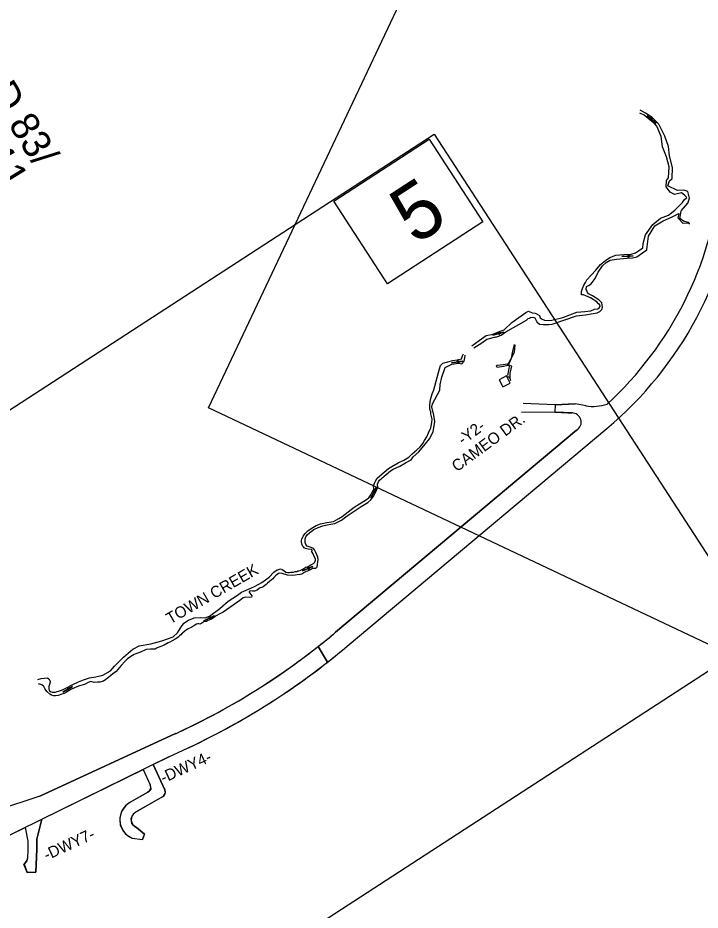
# Model space of a CAD drawing. Extents: x 555292 to 2368606, y 503623 to 1171444.
# Drawn here: x 2359845 to 2361046, y 1163245 to 1164815 of the extents above; entities that cross this region are included whole.
import ezdxf

# ---------------------------------------------------------------- set-up
doc = ezdxf.new("R2010")
doc.units = 0
for name, color, linetype in [('Default', 7, 'Continuous'), ('Exist Hydro Stream or Body of Water', 7, 'Continuous'), ('Exist Roads EOT', 7, 'Continuous'), ('Prop DSN Text', 7, 'Continuous'), ('Prop EOT', 7, 'Continuous'), ('Prop Shade Light', 7, 'Continuous'), ('Sheet North Arrow CELL', 7, 'Continuous'), ('Sheet Title CELL', 7, 'Continuous')]:
    doc.layers.add(name, color=color, linetype=linetype)

msp = doc.modelspace()

# ---------------------------------------------------------------- linework, layer by layer
at = {"layer": 'Default'}
for p, q in [((2360960.4, 1164635.9), (2360960.4, 1164635.9)), ((2360917.7, 1164395.2), (2360917.7, 1164395.2)), ((2360690.4, 1164259.1), (2360690.4, 1164259.1)), ((2360617.9, 1164209.3), (2360617.9, 1164209.3)), ((2360470.8, 1163979.1), (2360470.8, 1163979.1)), ((2360354.8, 1163845.5), (2360354.8, 1163845.5)), ((2360181.3, 1163758.1), (2360181.3, 1163758.1)), ((2359932.6, 1163633.2), (2359932.6, 1163633.2))]:
    msp.add_line(p, q, dxfattribs=at)
for points in [[(2360958.9, 1164634.1), (2360958, 1164635.9), (2360956.9, 1164637.6), (2360955.6, 1164639.3), (2360954.2, 1164640.8), (2360952.6, 1164642.2), (2360968.1, 1164629.5), (2360952.6, 1164642.2), (2360954.3, 1164640.9), (2360956.1, 1164639.9), (2360957.9, 1164639), (2360959.9, 1164638.2), (2360961.8, 1164637.6)], [(2360917.5, 1164397.5), (2360919.5, 1164396.9), (2360921.5, 1164396.4), (2360923.6, 1164396), (2360925.6, 1164395.8), (2360927.7, 1164395.9), (2360907.7, 1164394.6), (2360927.7, 1164395.9), (2360925.6, 1164395.7), (2360923.6, 1164395.2), (2360921.6, 1164394.6), (2360919.7, 1164393.9), (2360917.8, 1164393)], [(2360689.7, 1164261.3), (2360691.7, 1164261), (2360693.8, 1164261), (2360695.9, 1164261.1), (2360698, 1164261.4), (2360699.9, 1164261.9), (2360680.8, 1164256.2), (2360699.9, 1164261.9), (2360698, 1164261.3), (2360696.1, 1164260.4), (2360694.3, 1164259.3), (2360692.6, 1164258.2), (2360691, 1164256.9)], [(2360617.6, 1164211.5), (2360619.6, 1164211), (2360621.6, 1164210.7), (2360623.7, 1164210.5), (2360625.8, 1164210.5), (2360627.8, 1164210.7), (2360608.1, 1164207.8), (2360627.8, 1164210.7), (2360625.8, 1164210.3), (2360623.8, 1164209.7), (2360621.9, 1164209), (2360620, 1164208), (2360618.3, 1164207)], [(2360468.7, 1163980.1), (2360470.3, 1163981.5), (2360471.8, 1163982.9), (2360473.1, 1163984.5), (2360474.3, 1163986.2), (2360475.3, 1163988), (2360466.3, 1163970.2), (2360475.3, 1163988), (2360474.5, 1163986.2), (2360473.8, 1163984.2), (2360473.3, 1163982.1), (2360473, 1163980.1), (2360472.8, 1163978.1)], [(2360353.9, 1163847.6), (2360355.9, 1163847.6), (2360358, 1163847.8), (2360360.1, 1163848.2), (2360362.1, 1163848.7), (2360364, 1163849.5), (2360345.6, 1163841.5), (2360364, 1163849.5), (2360362.1, 1163848.6), (2360360.4, 1163847.5), (2360358.7, 1163846.2), (2360357.1, 1163844.8), (2360355.7, 1163843.4)], [(2360180.3, 1163760.2), (2360182.3, 1163760.3), (2360184.4, 1163760.6), (2360186.4, 1163761.1), (2360188.4, 1163761.7), (2360190.3, 1163762.6), (2360172.4, 1163753.7), (2360190.3, 1163762.6), (2360188.5, 1163761.6), (2360186.8, 1163760.4), (2360185.2, 1163759.1), (2360183.7, 1163757.6), (2360182.3, 1163756.1)], [(2359931.5, 1163635.2), (2359933.5, 1163635.5), (2359935.5, 1163636), (2359937.5, 1163636.6), (2359939.4, 1163637.4), (2359941.2, 1163638.4), (2359924.1, 1163628.1), (2359941.2, 1163638.4), (2359939.5, 1163637.3), (2359937.9, 1163635.9), (2359936.4, 1163634.5), (2359935, 1163632.9), (2359933.8, 1163631.3)]]:
    msp.add_lwpolyline(points, dxfattribs=at)
at = {"layer": 'Exist Hydro Stream or Body of Water'}
msp.add_line((2360706.9, 1164185.3), (2360710.5, 1164204.2), dxfattribs=at)
for points in [[(2360969.1, 1164624), (2360965.8, 1164628.3), (2360957.7, 1164634.6), (2360946.9, 1164643.4), (2360939.2, 1164646.9)], [(2360973, 1164627.5), (2360969, 1164632), (2360961.4, 1164639.4), (2360949.6, 1164647.1), (2360940, 1164652.2)], [(2360937.2, 1164404.8), (2360944.9, 1164410), (2360945, 1164417.6), (2360949.6, 1164432.9), (2360962.4, 1164451.2), (2360975.8, 1164462.4), (2360989.6, 1164467.7), (2361001.1, 1164476.1), (2361014.7, 1164489.6), (2361017.7, 1164494.8), (2361022.4, 1164498.9), (2361017.8, 1164502.8), (2361012.6, 1164507), (2361000.3, 1164504.1), (2360992.7, 1164508.2), (2360985.8, 1164517.6), (2360986.3, 1164528.3), (2360989.9, 1164533.5), (2360991, 1164552.5), (2360986.5, 1164570.3), (2360979.3, 1164587.7), (2360977, 1164605.8), (2360969.1, 1164624)], [(2361011.9, 1164475), (2361023.7, 1164488.8), (2361026.9, 1164497.4), (2361023.6, 1164509.2), (2361016.6, 1164511.7), (2361005.5, 1164510.9), (2360988.8, 1164519.2), (2360991.5, 1164528), (2360996.3, 1164532.1), (2360997.1, 1164551.2), (2360991.4, 1164572.2), (2360989.7, 1164588.6), (2360983.6, 1164606.4), (2360973, 1164627.5)], [(2360944.4, 1164401.3), (2360951.6, 1164406.4), (2360952.6, 1164411.7), (2360954.4, 1164430.6), (2360966, 1164448.7), (2360980.5, 1164457.6), (2360995.1, 1164464.1), (2361008.3, 1164470.6)], [(2361026.8, 1164451.8), (2361026.1, 1164452.1), (2361024.6, 1164453.5), (2361015.4, 1164453), (2361006.9, 1164462.2), (2361008.5, 1164470.3)], [(2361027.1, 1164452.4), (2361027.1, 1164452.8), (2361025.1, 1164454.9), (2361016, 1164457.1), (2361009.7, 1164461.8), (2361011.9, 1164474.6)], [(2360784.5, 1164282.6), (2360803.9, 1164287.7), (2360828.8, 1164297.1), (2360842.4, 1164298), (2360852.9, 1164299.1), (2360859.9, 1164302.3), (2360865.6, 1164302.6), (2360867.7, 1164304.7), (2360869.8, 1164306.9), (2360868.9, 1164309.7), (2360866.7, 1164311.6), (2360863.8, 1164315), (2360852.6, 1164322.1), (2360840.4, 1164327.2), (2360836.9, 1164327.5), (2360836.8, 1164333.2), (2360838.7, 1164338.5), (2360841, 1164344.2), (2360843.9, 1164349), (2360845.9, 1164354), (2360853.6, 1164361.9), (2360861.8, 1164370.8), (2360870.4, 1164380.6), (2360878.8, 1164387.9), (2360886.4, 1164392.9), (2360897.4, 1164397), (2360911.3, 1164398.3), (2360924.2, 1164399), (2360931.9, 1164401.2), (2360937.2, 1164404.8)], [(2360785.3, 1164276), (2360805.6, 1164282.6), (2360828.2, 1164290.5), (2360843.9, 1164292), (2360853.9, 1164293.8), (2360864.1, 1164295.9), (2360868.8, 1164298.2), (2360872.3, 1164301.7), (2360873.9, 1164305.8), (2360873.4, 1164309.7), (2360872.3, 1164313.4), (2360867.4, 1164318.5), (2360856.3, 1164325.6), (2360849.3, 1164329.3), (2360847.1, 1164331.6), (2360846.6, 1164334.1), (2360844.7, 1164336.5), (2360845.8, 1164341.8), (2360848.9, 1164344.1), (2360853.9, 1164346.7), (2360861.1, 1164356.2), (2360866, 1164367.4), (2360873.7, 1164378.2), (2360880.1, 1164384.5), (2360887.4, 1164388.6), (2360898.6, 1164390.4), (2360916.5, 1164391.7), (2360926.8, 1164392.4), (2360934.3, 1164394.2), (2360944.4, 1164401.3)], [(2360714.1, 1164279), (2360738.9, 1164296.4), (2360743.4, 1164298.9), (2360749.7, 1164295.5), (2360755.2, 1164294.9), (2360758.9, 1164293.3), (2360762.6, 1164291), (2360764, 1164287.2), (2360767.5, 1164284.5), (2360771.7, 1164283.1), (2360778.7, 1164282), (2360784.5, 1164282.6)], [(2360643.9, 1164237.7), (2360656.8, 1164247.2), (2360668.9, 1164256.1), (2360681.1, 1164257.9), (2360693.9, 1164263.3), (2360700.4, 1164266), (2360714.1, 1164279)], [(2360703.6, 1164262.5), (2360739.8, 1164282.9), (2360742.9, 1164285.7), (2360745, 1164286.5), (2360747.2, 1164287.3), (2360749.9, 1164288.1), (2360752.6, 1164287.5), (2360754.5, 1164286.8), (2360755.9, 1164284.8), (2360757.9, 1164279.7), (2360762.7, 1164275.6), (2360770, 1164275.4), (2360779, 1164275.3), (2360785.3, 1164276)], [(2360686.3, 1164253.1), (2360695.5, 1164256.3), (2360703.6, 1164262.5)], [(2360647.3, 1164234.3), (2360661.1, 1164242.7), (2360670.3, 1164249.2), (2360686, 1164253.2)], [(2360706.8, 1164184.5), (2360707.4, 1164183.4), (2360708.6, 1164183.4), (2360710.5, 1164180.7), (2360712.1, 1164176.4), (2360711.5, 1164182.8), (2360711.2, 1164189.3), (2360714, 1164201.6), (2360706.3, 1164202.8), (2360719.1, 1164226.4), (2360720.2, 1164239.4)], [(2360709.5, 1164206.6), (2360713.7, 1164215.7), (2360715.3, 1164225.4), (2360718.8, 1164240.1)], [(2360581.1, 1164175.5), (2360586.8, 1164197.3), (2360588.6, 1164203.2), (2360593, 1164207.2), (2360610.1, 1164211.9), (2360618.1, 1164213.1), (2360625.7, 1164214.7), (2360627.5, 1164220), (2360629.1, 1164223.8)], [(2360587.6, 1164159.9), (2360588, 1164169.8), (2360590.7, 1164182.5), (2360596.9, 1164199.8), (2360608.8, 1164205.2), (2360620.4, 1164207), (2360626, 1164206.1), (2360630.3, 1164210.7), (2360631.5, 1164216.8), (2360632, 1164221.1)], [(2360686.7, 1164202.3), (2360688.6, 1164203.9), (2360699, 1164204.7), (2360709.3, 1164206.4)], [(2360686.7, 1164202), (2360688.4, 1164200.4), (2360699.4, 1164202.1), (2360710.1, 1164204.1)], [(2360711, 1164171.9), (2360704.7, 1164184.6), (2360691.7, 1164177.8), (2360698.6, 1164165.7), (2360711, 1164171.9)], [(2360539, 1164047.7), (2360546.7, 1164054.6), (2360553, 1164059.8), (2360557.5, 1164066), (2360560.6, 1164071), (2360564.6, 1164077.8), (2360567.8, 1164084.8), (2360571.4, 1164093.5), (2360573.3, 1164102.7), (2360573.8, 1164108.8), (2360571.8, 1164118.1), (2360571.5, 1164121.6), (2360569.8, 1164126.5), (2360569.7, 1164131.9), (2360570.3, 1164140), (2360571.7, 1164145.1), (2360574.2, 1164153), (2360576.8, 1164160.1), (2360581.1, 1164175.5)], [(2360540.7, 1164042.2), (2360550.3, 1164051.2), (2360561.7, 1164064.8), (2360569.4, 1164073.9), (2360575.5, 1164086.3), (2360578.8, 1164104.4), (2360577.1, 1164115.5), (2360573.2, 1164130.3), (2360574.4, 1164135.5), (2360587.6, 1164159.9)], [(2360436.5, 1163953.6), (2360446.1, 1163959.8), (2360456.6, 1163966.4), (2360462.3, 1163970.2), (2360466.1, 1163975.7), (2360471.2, 1163985.8), (2360470.6, 1163990.5), (2360472.7, 1163995.8), (2360474.7, 1164000.7), (2360477.4, 1164004.6), (2360481.8, 1164009), (2360497.3, 1164022), (2360503, 1164025.5), (2360514.1, 1164031.6), (2360524.3, 1164036.3), (2360532.7, 1164041.6), (2360539, 1164047.7)], [(2360438.4, 1163948), (2360449.3, 1163954.9), (2360460.5, 1163961.9), (2360466.2, 1163966.6), (2360470.6, 1163973), (2360475.2, 1163982), (2360478.2, 1163988.8), (2360477.7, 1163994.2), (2360479.3, 1163998.2), (2360481.4, 1164001.2), (2360485.4, 1164005.1), (2360500.4, 1164017.8), (2360505.5, 1164020.9), (2360517.2, 1164026), (2360526.8, 1164031.8), (2360537, 1164036.9), (2360540.7, 1164042.2)], [(2360344.8, 1163897.3), (2360347, 1163902.7), (2360350.6, 1163907.7), (2360355.3, 1163912), (2360360.9, 1163916.2), (2360369.8, 1163921.6), (2360377.2, 1163924.2), (2360388.7, 1163926.7), (2360400.2, 1163928.4), (2360410, 1163934.1), (2360415.5, 1163937.6), (2360436.5, 1163953.6)], [(2360350.5, 1163898.3), (2360351.4, 1163901.7), (2360354.1, 1163905.2), (2360358.9, 1163909.4), (2360365.6, 1163914.3), (2360373.6, 1163917.9), (2360381.4, 1163920.8), (2360389, 1163922.8), (2360395.4, 1163923.8), (2360402.8, 1163925.2), (2360414.5, 1163931.2), (2360424.1, 1163938.5), (2360438.2, 1163947.9)], [(2360340.6, 1163835.5), (2360344.6, 1163836.5), (2360348.3, 1163838.9), (2360352.6, 1163841.3), (2360355.4, 1163842), (2360357.6, 1163842.8), (2360359.8, 1163843.9), (2360363.6, 1163846.3), (2360365.6, 1163846.6), (2360367.7, 1163846.5), (2360369, 1163846.5), (2360370.1, 1163846.8), (2360370.9, 1163847.4), (2360371.4, 1163848.6), (2360372, 1163852.9), (2360372.7, 1163857.6), (2360373.2, 1163861.9), (2360372.6, 1163865.9), (2360371.2, 1163869.7), (2360369.4, 1163873.9), (2360367.1, 1163878.5), (2360364.9, 1163880.9), (2360363.7, 1163881.9), (2360359, 1163883.2), (2360353.9, 1163884.9), (2360351.6, 1163888), (2360350.5, 1163891.4), (2360350.5, 1163898.3)], [(2360341.9, 1163842.4), (2360346.2, 1163844.7), (2360351.9, 1163848), (2360355.9, 1163849.3), (2360360.6, 1163852.1), (2360362.8, 1163853.8), (2360365.4, 1163854.9), (2360367.7, 1163857.1), (2360368.4, 1163860.6), (2360368.4, 1163862.8), (2360366.6, 1163867.1), (2360364.8, 1163871.5), (2360362.9, 1163874.6), (2360361.7, 1163876.2), (2360362.7, 1163877.1), (2360362.6, 1163878.2), (2360361.9, 1163879.3), (2360361.3, 1163879.5), (2360356, 1163880), (2360353.3, 1163880.4), (2360351, 1163881.3), (2360349, 1163882.5), (2360347.4, 1163883.8), (2360345.9, 1163885.5), (2360345, 1163887.8), (2360344.3, 1163891.4), (2360344, 1163895.3), (2360344.8, 1163897.3)], [(2359880.3, 1163650.6), (2359885.9, 1163652.5), (2359891.1, 1163653.2), (2359897, 1163653.7), (2359899.2, 1163651.8), (2359901.5, 1163647.4), (2359901.2, 1163643.3), (2359899.4, 1163638), (2359899.2, 1163634.4), (2359900, 1163631), (2359902.2, 1163629.4), (2359905.5, 1163628.3), (2359911.2, 1163628.1), (2359914.3, 1163629.3), (2359920.3, 1163631.4), (2359924.8, 1163633.2), (2359930.5, 1163636), (2359940.4, 1163641.5), (2359951.5, 1163646.2), (2359960.3, 1163650), (2359971, 1163653.8), (2359982.2, 1163655.3), (2359994.2, 1163658.4), (2360008.1, 1163666.1), (2360014.7, 1163674.3), (2360030.5, 1163689.6), (2360047.2, 1163703.9), (2360058.6, 1163709.6), (2360079.1, 1163713.3), (2360098.4, 1163718.7), (2360118.4, 1163725.7), (2360125.8, 1163732.7), (2360131.7, 1163742.1), (2360137, 1163749.8), (2360145.3, 1163754.9), (2360155.1, 1163759.1), (2360165.5, 1163759.9), (2360174.6, 1163759.2), (2360182.3, 1163762.2), (2360200.2, 1163775.5), (2360215.2, 1163788.6), (2360231.5, 1163799), (2360238.7, 1163804.5), (2360250.8, 1163809.8), (2360261.5, 1163814.3), (2360274.5, 1163821.4), (2360287, 1163830.7), (2360295.2, 1163839.3), (2360301.1, 1163843.7), (2360303.4, 1163844)], [(2360303.4, 1163844), (2360307.1, 1163845.2), (2360310, 1163844.3), (2360312.7, 1163842.1), (2360316.7, 1163839.7), (2360320.1, 1163838.8), (2360322.7, 1163839), (2360325, 1163839.5), (2360327.5, 1163839.7), (2360330.1, 1163839.7), (2360332.8, 1163840.6), (2360334.3, 1163840.4), (2360336, 1163840.7), (2360337.7, 1163841.9), (2360339.3, 1163841.9), (2360341.9, 1163842.4)], [(2360305.3, 1163837.8), (2360303.3, 1163836.9), (2360301.4, 1163835.5), (2360298.3, 1163832.8), (2360295.4, 1163830.2), (2360293.3, 1163828), (2360290.8, 1163825.2), (2360288, 1163823.1), (2360284.1, 1163819.8), (2360281.8, 1163818), (2360276.8, 1163813.9), (2360274.5, 1163812.6), (2360271.3, 1163811.7), (2360269.4, 1163810.5), (2360265.8, 1163807.6), (2360261.4, 1163805.9), (2360257.7, 1163806.2), (2360254.8, 1163806.4), (2360253, 1163806), (2360252.2, 1163805.4), (2360252.1, 1163804.3), (2360253.1, 1163802.5), (2360256.5, 1163797.7), (2360256.2, 1163795.6), (2360252.6, 1163794.6), (2360246.2, 1163795.2), (2360241.5, 1163794.1), (2360235.5, 1163789.8), (2360229.4, 1163785.2), (2360223.9, 1163781.3), (2360206.1, 1163769), (2360200.1, 1163766), (2360193.7, 1163762.5), (2360192, 1163761.3), (2360190.8, 1163760.1), (2360188.2, 1163758.3), (2360185.8, 1163756.6), (2360183, 1163755.5), (2360179.3, 1163754.4), (2360176.6, 1163752.8), (2360175.5, 1163752.4), (2360171.8, 1163751.9), (2360170.1, 1163751), (2360168.6, 1163750), (2360165.3, 1163748.2), (2360163.2, 1163748.5), (2360161.6, 1163748.4), (2360159.4, 1163747.8), (2360156.3, 1163745.9), (2360150.9, 1163742.8), (2360143.5, 1163739), (2360138.8, 1163735.7), (2360135.1, 1163732.9), (2360134, 1163732.1), (2360131.5, 1163729.3), (2360129.1, 1163727.4), (2360127.2, 1163725.2), (2360124.8, 1163723.5), (2360121.5, 1163721.4), (2360116.5, 1163718.5), (2360112.5, 1163716.2), (2360109.3, 1163714.9), (2360102.3, 1163711), (2360090.3, 1163706.3), (2360086.4, 1163704.2), (2360078.5, 1163703.8), (2360070.7, 1163703.2), (2360060.5, 1163698.9), (2360052.6, 1163695.9), (2360049.3, 1163694.4), (2360043.4, 1163690.8), (2360037.6, 1163686.8), (2360033.2, 1163682.3), (2360026.7, 1163675.2), (2360018.1, 1163664.6), (2360011.9, 1163660.4), (2360008.5, 1163657.8), (2360004.1, 1163654.4), (2359999.4, 1163650.5), (2359995.4, 1163647.8), (2359989, 1163646.1), (2359984.8, 1163645.7), (2359979.2, 1163645.6), (2359973.2, 1163646.8), (2359968.8, 1163645.3), (2359961.9, 1163642), (2359953.4, 1163639.5), (2359948.4, 1163637.8), (2359943.1, 1163635.4), (2359939, 1163633.4), (2359930.3, 1163628.2), (2359926.4, 1163625.9), (2359922.4, 1163624.5), (2359915.6, 1163622.4), (2359911.4, 1163621.7), (2359908.2, 1163622.1), (2359904.1, 1163622.8), (2359901, 1163624.8), (2359896.1, 1163629.2), (2359892.7, 1163633.6), (2359890.6, 1163638.5), (2359887.3, 1163641.3), (2359881.4, 1163643)], [(2360340.6, 1163835.5), (2360328.8, 1163833.4), (2360319.2, 1163834.4), (2360310, 1163837.1), (2360305.3, 1163837.8)]]:
    msp.add_lwpolyline(points, dxfattribs=at)
at = {"layer": 'Exist Roads EOT'}
for p, q in [((2360790.7, 1164134.1), (2360733.9, 1164136.1)), ((2360790, 1164120.9), (2360731.3, 1164120.1))]:
    msp.add_line(p, q, dxfattribs=at)
at = {"layer": 'Prop EOT'}
for p, q in [((2360790.7, 1164134.1), (2360790, 1164120.9)), ((2360790.7, 1164134.1), (2360825.5, 1164135.6)), ((2360813.3, 1164135.3), (2360825.5, 1164135.6)), ((2360844.7, 1164132), (2360825.5, 1164135.6)), ((2360821, 1164119.5), (2360790, 1164120.9)), ((2360819.5, 1164119.6), (2360812.7, 1164119.9)), ((2360424.6, 1163709.1), (2360881.4, 1164092.1)), ((2360404, 1163733.6), (2360828.2, 1164089.3)), ((2359883.3, 1163445.3), (2360122.4, 1163555.3)), ((2360110.8, 1163514.7), (2360135.7, 1163526.2)), ((2360110.8, 1163514.7), (2359719.7, 1163322.7)), ((2360083.2, 1163501.1), (2360103.6, 1163456.7)), ((2360065.2, 1163492.3), (2360077.8, 1163465)), ((2360073.6, 1163452.2), (2360042.1, 1163434.2)), ((2359883.3, 1163445.3), (2359787.8, 1163413.5)), ((2360099.5, 1163443.9), (2360052, 1163416.9)), ((2359886.8, 1163404.7), (2359878.1, 1163369.8)), ((2359857.6, 1163390.4), (2359862.2, 1163366.2)), ((2360053.6, 1163390), (2360067.8, 1163378.2)), ((2359878.1, 1163369.8), (2359878.2, 1163352)), ((2360045.9, 1163371.6), (2360064.1, 1163369.3)), ((2360067.8, 1163378.2), (2360064.1, 1163369.3)), ((2359862.2, 1163366.2), (2359862.2, 1163351.9)), ((2359878.2, 1163352), (2359876.6, 1163311.5))]:
    msp.add_line(p, q, dxfattribs=at)
for points in [[(2359862.2, 1163351.9), (2359862.1, 1163335.7)], [(2359876.6, 1163311.5), (2359861, 1163310.9), (2359855.5, 1163325.7)]]:
    msp.add_lwpolyline(points, dxfattribs=at)
for centre, radius, start, end in [((2360457.9, 1164597.1), 627, 312.546, 353.9875), ((2360457.9, 1164597.1), 659, 309.9822, 353.9875), ((2360856.7, 1164211.6), 80.5, 261.3878, 288.2173), ((2360820.1, 1164103.4), 16.2, 299.8467, 92.0647), ((2359598.3, 1164694.5), 1254, 294.7046, 309.9822), ((2359598.3, 1164694.5), 1286, 294.7046, 309.9822), ((2360068.7, 1163460.9), 10, 299.6462, 24.7046), ((2360094.5, 1163452.6), 10, 299.6462, 24.7046), ((2360059.4, 1163403.8), 35, 119.6462, 247.1741), ((2360059.4, 1163403.8), 15, 119.6462, 247.1741), ((2359842.2, 1163341.6), 20.7, 309.8688, 343.6043)]:
    msp.add_arc(centre, radius, start, end, dxfattribs=at)
at = {"layer": 'Prop Shade Light'}
for p, q in [((2360825.5, 1164135.6), (2360813.3, 1164135.3)), ((2360844.7, 1164132), (2360825.5, 1164135.6)), ((2360812.7, 1164119.9), (2360819.5, 1164119.6)), ((2360424.6, 1163709.1), (2360881.4, 1164092.1)), ((2360828.2, 1164089.3), (2360404, 1163733.6)), ((2360373.2, 1163708.6), (2360389.9, 1163681.1)), ((2360389.9, 1163681.1), (2360373.2, 1163708.6)), ((2360122.4, 1163555.3), (2359883.3, 1163445.3)), ((2360110.8, 1163514.7), (2360135.7, 1163526.2)), ((2359883.3, 1163445.3), (2359787.8, 1163413.5))]:
    msp.add_line(p, q, dxfattribs=at)
for points in [[(2360813.3, 1164135.3), (2360790.7, 1164134.1), (2360790, 1164120.9), (2360812.7, 1164119.9)], [(2359760, 1163342.4), (2359857.6, 1163390.4), (2359862.2, 1163366.2), (2359862.2, 1163351.9), (2359862.1, 1163335.7), (2359859.8, 1163330.1), (2359855.7, 1163325.6), (2359861, 1163310.9), (2359876.6, 1163311.5), (2359878.2, 1163352), (2359878.2, 1163352), (2359878.1, 1163369.8), (2359886.8, 1163404.7), (2360065.2, 1163492.3), (2360077.8, 1163465), (2360078.9, 1163457.9), (2360077, 1163455.4), (2360073, 1163452), (2360042.1, 1163434.2), (2360034.7, 1163429.1), (2360027, 1163418.3), (2360024.6, 1163407.3), (2360024.9, 1163394.4), (2360030.5, 1163383.1), (2360037.3, 1163376.8), (2360045.9, 1163371.6), (2360064.1, 1163369.3), (2360067.8, 1163378.2), (2360053.6, 1163390), (2360048.2, 1163394), (2360045.5, 1163397.3), (2360044.4, 1163405.5), (2360046.5, 1163412.1), (2360052, 1163416.9), (2360101.1, 1163445.1), (2360104.4, 1163451), (2360103.6, 1163456.7), (2360083.2, 1163501.1), (2360110.8, 1163514.7)]]:
    msp.add_lwpolyline(points, dxfattribs=at)
for centre, radius, start, end in [((2360457.9, 1164597.1), 627, 312.546, 353.9875), ((2360457.9, 1164597.1), 659, 309.9822, 353.9875), ((2360856.7, 1164211.6), 80.5, 261.3878, 288.2173), ((2360820.1, 1164103.4), 16.2, 299.8467, 92.0647), ((2359598.3, 1164694.5), 1254, 308.1676, 309.9822), ((2359598.3, 1164694.5), 1254, 294.7046, 308.1676), ((2359598.3, 1164694.5), 1286, 307.9968, 309.9822), ((2359598.3, 1164694.5), 1286, 294.7046, 307.9968)]:
    msp.add_arc(centre, radius, start, end, dxfattribs=at)
at = {"layer": 'Sheet Title CELL'}
for points in [[(2361846.2, 1165184.1), (2361134.1, 1163677.4), (2360180.2, 1164128.3), (2360892.3, 1165635)], [(2361152.4, 1163725.3), (2359754.7, 1162817.6), (2359180.1, 1163702.5), (2360577.7, 1164610.1)], [(2360400.8, 1164492.2), (2360568.6, 1164601.2), (2360663.1, 1164455.7), (2360495.4, 1164346.7)]]:
    msp.add_lwpolyline(points, close=True, dxfattribs=at)

# ---------------------------------------------------------------- texts
at = {"layer": 'Default'}
msp.add_text('5', height=100, rotation=33.0023, dxfattribs=at).set_placement((2360543.9, 1164414))
at = {"layer": 'Prop DSN Text'}
for s, rotation, p in [('CAMEO DR.', 36.3669, (2360617.6, 1164015.1)), ('-Y2-', 36.3669, (2360628.2, 1164062.3)), ('TOWN CREEK', 29.9402, (2360113.1, 1163747.4)), ('-DWY4-', 24.7046, (2360101.2, 1163467.7)), ('-DWY7-', 24.7046, (2359895.8, 1163331.9))]:
    msp.add_text(s, height=20, rotation=rotation, dxfattribs=at).set_placement(p)
at = {"layer": 'Sheet North Arrow CELL'}
for s, p in [('NAD 83/', (2359743.7, 1164763.7)), ('NA 2011', (2359687.8, 1164729.4))]:
    msp.add_text(s, height=50, rotation=301.5234, dxfattribs=at).set_placement(p)

doc.saveas('drawing.dxf')
